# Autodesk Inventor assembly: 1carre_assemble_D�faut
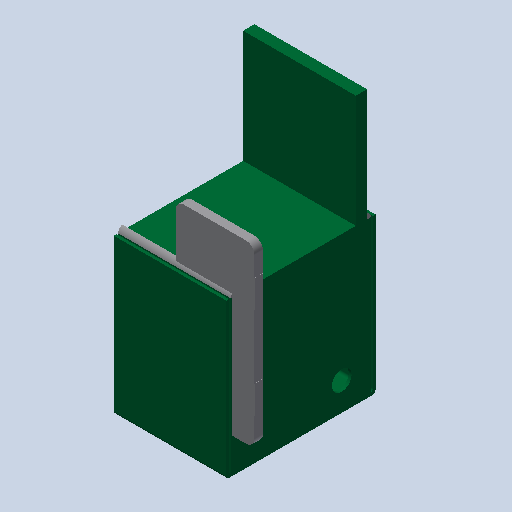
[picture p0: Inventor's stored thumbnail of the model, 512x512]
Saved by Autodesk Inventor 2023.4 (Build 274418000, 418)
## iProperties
Created: 2011-01
Part Number: 1carre_assemble_D�faut
Document SubType Name: Assembly
Designer: eric
Mass: 25.4449 g
Surface Area: 362.356 cm^2
Volume: 25.4449 cm^3
Density: 1 g/cm^3
Author: eric
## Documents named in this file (6)
- C:\Users\bruno\Documents\1-Cours-2024-25\TSsI\7-Dynamique\chariot de golf\chariot_de_golf\chariot_de_golf_trolem\1carre_assemble_Defaut.iam
- C:\Users\bruno\Documents\1-Cours-2024-25\TSsI\7-Dynamique\chariot de golf\chariot_de_golf\chariot_de_golf_trolem\bead40_Defaut.ipt
- C:\Users\bruno\Documents\1-Cours-2024-25\TSsI\7-Dynamique\chariot de golf\chariot_de_golf\chariot_de_golf_trolem\1plaque_avant_boitier_Defaut.ipt
- C:\Users\bruno\Documents\1-Cours-2024-25\TSsI\7-Dynamique\chariot de golf\chariot_de_golf\chariot_de_golf_trolem\1plaque_arriere_Defaut.ipt
- C:\Users\bruno\Documents\1-Cours-2024-25\TSsI\7-Dynamique\chariot de golf\chariot_de_golf\chariot_de_golf_trolem\bead41_Defaut.ipt
- C:\Users\bruno\Documents\1-Cours-2024-25\TSsI\7-Dynamique\chariot de golf\chariot_de_golf\chariot_de_golf_trolem\1carre_support_Defaut.ipt
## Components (5 placed, 5 different names)
1. bead40_Defaut:1
2. 1plaque_avant_boitier_Defaut:1
3. 1plaque_arriere_Defaut:1
4. bead41_Defaut:1
5. 1carre_support_Defaut:1
